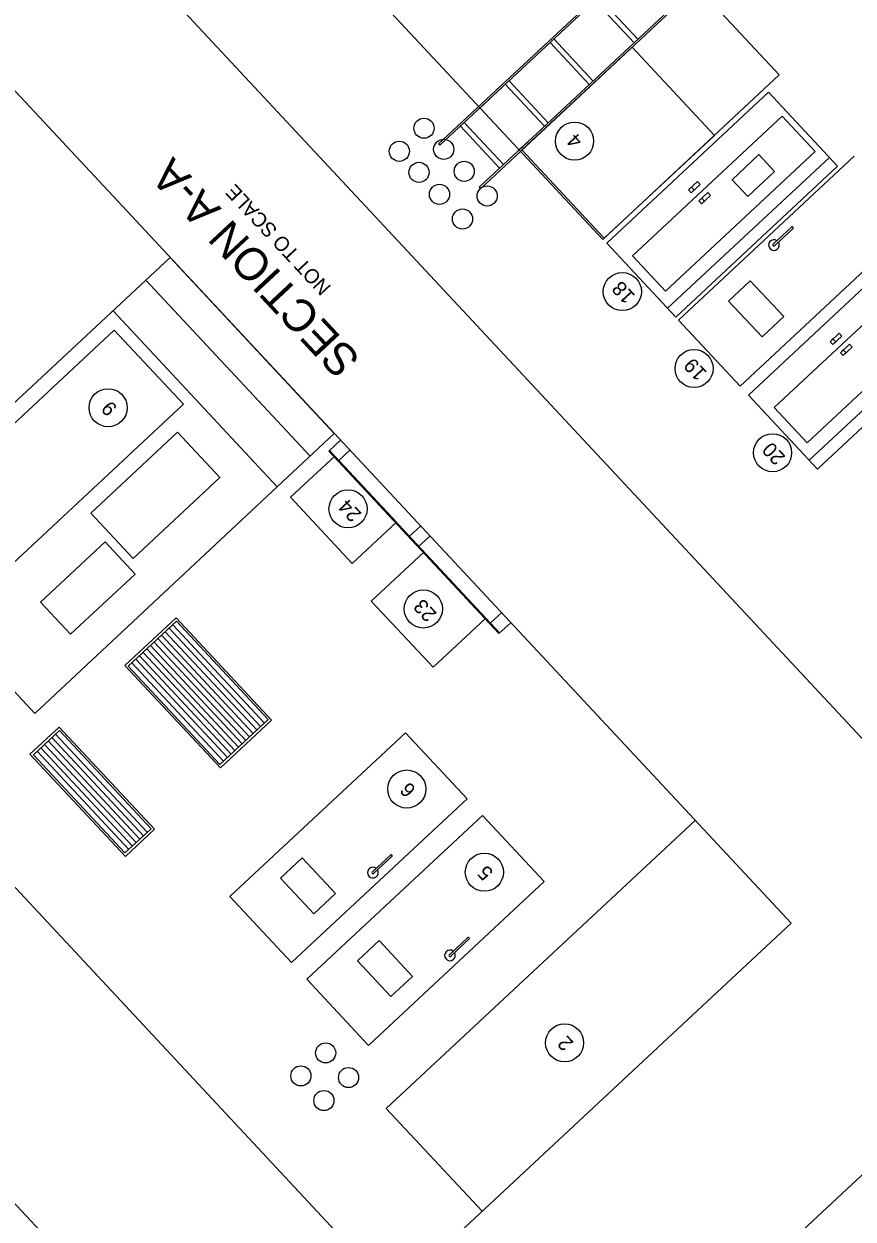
# Model space of a CAD drawing. Extents: x 1121979 to 1130574, y 1838676 to 1848573.
# Drawn here: x 1129646.59 to 1129660.33, y 1839345.74 to 1839365.55 of the extents above; entities that cross this region are included whole.
import ezdxf

# ---------------------------------------------------------------- set-up
doc = ezdxf.new("R2010")
doc.units = 0
for name, color, linetype in [('CLB-6', 7, 'Continuous'), ('GE-SHT-Clip Border', 7, 'Continuous'), ('GE-SHT-General', 7, 'Continuous'), ('HS_Dimensions and Text', 7, 'Continuous'), ('IPDC BUILDING RELATED', 7, 'Continuous'), ('IPDC-EXIST ELECT EQUIP', 7, 'Continuous'), ('IPDC-PROP ELECT CONDUIT', 7, 'Continuous'), ('IPDC-PROP ELECT EQUIP', 7, 'Continuous'), ('Level 4', 7, 'Continuous'), ('Sheets_General Details', 7, 'Continuous'), ('Sheets_Printer Plotting Border', 7, 'Continuous')]:
    doc.layers.add(name, color=color, linetype=linetype)

# ---------------------------------------------------------------- blocks, each defined once
blk = doc.blocks.new('CLB_61')
at = {"layer": 'CLB-6'}
for p, q in [((0.095, 18.288), (0, 18.288)), ((0, 18.288), (0, 0)), ((0.095, 18.288), (0.095, 0)), ((3.048, 18.288), (2.953, 18.288)), ((2.953, 18.288), (2.953, 0)), ((3.048, 18.288), (3.048, 0)), ((0.095, 16.891), (2.953, 16.891)), ((0.095, 16.637), (2.953, 16.637)), ((0.098, 15.621), (0.098, 14.859)), ((0.095, 13.843), (2.953, 13.843)), ((0.095, 13.589), (2.953, 13.589)), ((0.095, 10.795), (2.953, 10.795)), ((0.095, 10.541), (2.953, 10.541)), ((0.095, 7.747), (2.953, 7.747)), ((0.095, 7.493), (2.953, 7.493)), ((0.095, 4.699), (2.953, 4.699)), ((0.095, 4.445), (2.953, 4.445)), ((0.098, 3.429), (0.098, 2.667)), ((2.95, 2.667), (2.95, 3.429)), ((0.095, 1.651), (2.953, 1.651)), ((0.095, 1.397), (2.953, 1.397)), ((0.095, 0), (0, 0)), ((3.048, 0), (2.953, 0))]:
    blk.add_line(p, q, dxfattribs=at)

msp = doc.modelspace()

# ---------------------------------------------------------------- linework, layer by layer
at = {"layer": 'GE-SHT-Clip Border'}
msp.add_lwpolyline([(1129652.729, 1839339.252), (1129609.766, 1839385.33), (1129639.021, 1839412.608), (1129681.985, 1839366.531)], close=True, dxfattribs=at)
msp.add_lwpolyline([(1129652.729, 1839339.252), (1129609.766, 1839385.33), (1129639.021, 1839412.608), (1129681.985, 1839366.531)], close=True, dxfattribs=at)
msp.add_lwpolyline([(1129652.729, 1839339.252), (1129609.766, 1839385.33), (1129639.021, 1839412.608), (1129681.985, 1839366.531)], close=True, dxfattribs=at)
at = {"layer": 'GE-SHT-General'}
msp.add_lwpolyline([(1129652.729, 1839339.252), (1129609.766, 1839385.33), (1129640.484, 1839413.972), (1129683.448, 1839367.895)], close=True, dxfattribs=at)
at = {"layer": 'IPDC BUILDING RELATED'}
for p, q in [((1129642.1, 1839373.419), (1129661.457, 1839352.656)), ((1129639.942, 1839371.407), (1129659.302, 1839350.647)), ((1129652.719, 1839344.509), (1129633.359, 1839365.269)), ((1129659.302, 1839350.647), (1129652.719, 1839344.509))]:
    msp.add_line(p, q, dxfattribs=at)
at = {"layer": 'IPDC-EXIST ELECT EQUIP'}
for p, q in [((1129652.389, 1839371.914), (1129659.107, 1839364.708)), ((1129656.182, 1839361.98), (1129649.463, 1839369.186)), ((1129659.107, 1839364.708), (1129656.182, 1839361.98)), ((1129644.042, 1839357.05), (1129649.01, 1839361.682)), ((1129649.01, 1839361.682), (1129651.73, 1839358.766)), ((1129651.33, 1839358.391), (1129648.61, 1839361.309)), ((1129650.785, 1839357.882), (1129648.064, 1839360.8)), ((1129644.456, 1839357.097), (1129648.085, 1839360.48)), ((1129648.085, 1839360.48), (1129649.232, 1839359.249)), ((1129645.604, 1839355.866), (1129649.232, 1839359.249)), ((1129651.73, 1839358.766), (1129646.77, 1839354.124)), ((1129647.695, 1839357.446), (1129649.133, 1839358.787)), ((1129649.133, 1839358.787), (1129649.834, 1839358.035)), ((1129651.836, 1839358.653), (1129651.641, 1839358.472)), ((1129654.473, 1839355.458), (1129651.653, 1839358.482)), ((1129651.991, 1839358.487), (1129651.808, 1839358.317)), ((1129651.008, 1839357.708), (1129651.739, 1839358.39)), ((1129654.461, 1839355.448), (1129651.641, 1839358.472)), ((1129652.762, 1839357.293), (1129651.739, 1839358.39)), ((1129649.834, 1839358.035), (1129648.396, 1839356.694)), ((1129652.03, 1839356.611), (1129651.008, 1839357.708)), ((1129648.396, 1839356.694), (1129647.695, 1839357.446)), ((1129652.762, 1839357.293), (1129652.03, 1839356.611)), ((1129653.162, 1839357.231), (1129652.979, 1839357.061)), ((1129646.77, 1839354.124), (1129644.042, 1839357.05)), ((1129646.865, 1839355.97), (1129647.935, 1839356.967)), ((1129648.43, 1839356.436), (1129647.935, 1839356.967)), ((1129653.316, 1839357.065), (1129653.122, 1839356.884)), ((1129653.208, 1839356.792), (1129652.345, 1839355.987)), ((1129654.231, 1839355.695), (1129653.208, 1839356.792)), ((1129647.36, 1839355.439), (1129648.43, 1839356.436)), ((1129647.36, 1839355.439), (1129646.865, 1839355.97)), ((1129653.368, 1839354.89), (1129652.345, 1839355.987)), ((1129648.261, 1839354.919), (1129649.11, 1839355.71)), ((1129650.692, 1839354.013), (1129649.11, 1839355.71)), ((1129654.501, 1839355.795), (1129654.318, 1839355.624)), ((1129648.317, 1839354.907), (1129649.118, 1839355.654)), ((1129650.511, 1839353.909), (1129648.993, 1839355.538)), ((1129650.573, 1839353.966), (1129649.054, 1839355.595)), ((1129650.636, 1839354.025), (1129649.118, 1839355.654)), ((1129654.231, 1839355.695), (1129653.368, 1839354.89)), ((1129654.656, 1839355.629), (1129654.461, 1839355.448)), ((1129650.327, 1839353.737), (1129648.808, 1839355.366)), ((1129650.389, 1839353.794), (1129648.87, 1839355.423)), ((1129650.45, 1839353.851), (1129648.931, 1839355.48)), ((1129650.081, 1839353.508), (1129648.563, 1839355.137)), ((1129650.143, 1839353.565), (1129648.624, 1839355.194)), ((1129650.204, 1839353.622), (1129648.685, 1839355.251)), ((1129650.266, 1839353.679), (1129648.747, 1839355.308)), ((1129649.844, 1839353.222), (1129648.261, 1839354.919)), ((1129649.897, 1839353.336), (1129648.378, 1839354.965)), ((1129649.959, 1839353.393), (1129648.44, 1839355.022)), ((1129650.02, 1839353.45), (1129648.501, 1839355.079)), ((1129649.836, 1839353.278), (1129648.317, 1839354.907)), ((1129649.836, 1839353.278), (1129650.636, 1839354.025)), ((1129649.844, 1839353.222), (1129650.692, 1839354.013)), ((1129646.688, 1839353.452), (1129647.169, 1839353.9)), ((1129646.744, 1839353.441), (1129647.177, 1839353.844)), ((1129648.631, 1839352.155), (1129647.112, 1839353.784)), ((1129648.751, 1839352.204), (1129647.169, 1839353.9)), ((1129648.695, 1839352.215), (1129647.177, 1839353.844)), ((1129650, 1839351.089), (1129652.911, 1839353.803)), ((1129653.931, 1839352.708), (1129652.911, 1839353.803)), ((1129648.385, 1839351.926), (1129646.866, 1839353.555)), ((1129648.447, 1839351.983), (1129646.928, 1839353.612)), ((1129648.508, 1839352.041), (1129646.989, 1839353.67)), ((1129648.57, 1839352.098), (1129647.051, 1839353.727)), ((1129648.27, 1839351.755), (1129646.688, 1839353.452)), ((1129648.262, 1839351.812), (1129646.744, 1839353.441)), ((1129648.324, 1839351.869), (1129646.805, 1839353.498)), ((1129651.021, 1839349.995), (1129653.931, 1839352.708)), ((1129651.279, 1839349.718), (1129654.189, 1839352.432)), ((1129657.711, 1839352.353), (1129652.591, 1839347.579)), ((1129655.21, 1839351.337), (1129654.189, 1839352.432)), ((1129648.262, 1839351.812), (1129648.695, 1839352.215)), ((1129648.27, 1839351.755), (1129648.751, 1839352.204)), ((1129652.366, 1839351.502), (1129652.668, 1839351.784)), ((1129652.388, 1839351.478), (1129652.69, 1839351.76)), ((1129650.838, 1839351.395), (1129651.198, 1839351.731)), ((1129651.198, 1839351.731), (1129651.751, 1839351.138)), ((1129651.391, 1839350.802), (1129650.838, 1839351.395)), ((1129652.299, 1839348.623), (1129655.21, 1839351.337)), ((1129651.021, 1839349.995), (1129650, 1839351.089)), ((1129651.751, 1839351.138), (1129651.391, 1839350.802)), ((1129653.645, 1839350.131), (1129653.947, 1839350.412)), ((1129653.667, 1839350.107), (1129653.969, 1839350.389)), ((1129652.117, 1839350.024), (1129652.476, 1839350.359)), ((1129652.476, 1839350.359), (1129653.03, 1839349.766)), ((1129652.67, 1839349.431), (1129652.117, 1839350.024)), ((1129653.03, 1839349.766), (1129652.67, 1839349.431)), ((1129652.299, 1839348.623), (1129651.279, 1839349.718)), ((1129652.591, 1839347.579), (1129654.182, 1839345.873))]:
    msp.add_line(p, q, dxfattribs=at)
for centre in [(1129653.218, 1839363.825), (1129653.545, 1839363.475), (1129652.809, 1839363.443), (1129653.135, 1839363.093), (1129653.885, 1839363.11), (1129653.475, 1839362.729), (1129654.265, 1839362.702), (1129653.856, 1839362.32), (1129651.588, 1839348.498), (1129651.178, 1839348.117), (1129651.968, 1839348.09), (1129651.559, 1839347.708)]:
    msp.add_circle(centre, 0.167, dxfattribs=at)
for centre, radius, start, end in [((1129652.673, 1839351.766), 0.0183, 339.5896, 106.4047), ((1129652.371, 1839351.486), 0.0887, 52.4771, 31.2221), ((1129652.372, 1839351.485), 0.018, 108.471, 337.5232), ((1129653.952, 1839350.395), 0.0183, 339.5896, 106.4047), ((1129653.649, 1839350.115), 0.0887, 52.4771, 31.2221), ((1129653.65, 1839350.114), 0.018, 108.471, 337.5232)]:
    msp.add_arc(centre, radius, start, end, dxfattribs=at)
at = {"layer": 'IPDC-PROP ELECT CONDUIT'}
for p, q in [((1129657.254, 1839360.84), (1129659.936, 1839363.341)), ((1129659.601, 1839358.323), (1129662.283, 1839360.823))]:
    msp.add_line(p, q, dxfattribs=at)
for points in [[(1129660.073, 1839363.194), (1129658.93, 1839364.42), (1129656.248, 1839361.92), (1129657.391, 1839360.693)], [(1129659.7, 1839363.44), (1129659.155, 1839364.025), (1129656.673, 1839361.711), (1129657.219, 1839361.126)], [(1129659.029, 1839363.11), (1129658.77, 1839363.387), (1129658.325, 1839362.972), (1129658.583, 1839362.695)], [(1129657.796, 1839362.894), (1129657.75, 1839362.943), (1129657.601, 1839362.804), (1129657.646, 1839362.755)], [(1129657.601, 1839362.804), (1129657.646, 1839362.755), (1129657.695, 1839362.8), (1129657.649, 1839362.849)], [(1129657.966, 1839362.711), (1129657.92, 1839362.76), (1129657.771, 1839362.621), (1129657.817, 1839362.572)], [(1129657.771, 1839362.621), (1129657.817, 1839362.572), (1129657.865, 1839362.617), (1129657.82, 1839362.666)], [(1129662.42, 1839360.676), (1129661.277, 1839361.903), (1129658.595, 1839359.402), (1129659.738, 1839358.176)], [(1129662.047, 1839360.923), (1129661.502, 1839361.508), (1129659.02, 1839359.194), (1129659.566, 1839358.609)], [(1129660.143, 1839360.377), (1129660.097, 1839360.426), (1129659.948, 1839360.287), (1129659.994, 1839360.238)], [(1129659.948, 1839360.287), (1129659.994, 1839360.238), (1129660.042, 1839360.283), (1129659.996, 1839360.332)], [(1129660.313, 1839360.194), (1129660.268, 1839360.243), (1129660.118, 1839360.104), (1129660.164, 1839360.055)], [(1129660.118, 1839360.104), (1129660.164, 1839360.055), (1129660.212, 1839360.1), (1129660.167, 1839360.149)]]:
    msp.add_lwpolyline(points, close=True, dxfattribs=at)
at = {"layer": 'IPDC-PROP ELECT EQUIP'}
for p, q in [((1129654.84, 1839363.464), (1129656.669, 1839365.169)), ((1129656.669, 1839365.169), (1129658.032, 1839363.706)), ((1129656.204, 1839362.001), (1129658.032, 1839363.706)), ((1129654.84, 1839363.464), (1129656.204, 1839362.001)), ((1129657.435, 1839360.646), (1129660.346, 1839363.36)), ((1129658.456, 1839359.551), (1129661.366, 1839362.265)), ((1129659.011, 1839361.907), (1129659.313, 1839362.188)), ((1129659.033, 1839361.883), (1129659.335, 1839362.165)), ((1129658.626, 1839361.295), (1129658.267, 1839360.959)), ((1129659.179, 1839360.702), (1129658.626, 1839361.295)), ((1129658.267, 1839360.959), (1129658.82, 1839360.366)), ((1129658.82, 1839360.366), (1129659.179, 1839360.702)), ((1129657.435, 1839360.646), (1129658.456, 1839359.551))]:
    msp.add_line(p, q, dxfattribs=at)
for centre, radius, start, end in [((1129659.318, 1839362.171), 0.0183, 339.5896, 106.4046), ((1129659.018, 1839361.888), 0.0887, 54.7722, 33.5172), ((1129659.016, 1839361.89), 0.018, 108.471, 337.5232)]:
    msp.add_arc(centre, radius, start, end, dxfattribs=at)
at = {"layer": 'Level 4'}
for centre in [(1129655.713, 1839363.611), (1129656.505, 1839361.117), (1129657.694, 1839359.842), (1129647.983, 1839359.192), (1129658.995, 1839358.446), (1129651.959, 1839357.516), (1129653.207, 1839355.857), (1129652.933, 1839352.872), (1129654.219, 1839351.493), (1129655.548, 1839348.665)]:
    msp.add_circle(centre, 0.316, dxfattribs=at)
at = {"layer": 'Sheets_Printer Plotting Border'}
for centre in [(1129653.218, 1839363.825), (1129653.545, 1839363.475), (1129652.809, 1839363.443), (1129653.135, 1839363.093), (1129653.885, 1839363.11), (1129653.475, 1839362.729), (1129654.265, 1839362.702), (1129653.856, 1839362.32), (1129651.588, 1839348.498), (1129651.178, 1839348.117), (1129651.968, 1839348.09), (1129651.559, 1839347.708)]:
    msp.add_circle(centre, 0.167, dxfattribs=at)

# ---------------------------------------------------------------- block references
at = {"layer": 'IPDC-EXIST ELECT EQUIP', "xscale": 0.3332999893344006, "yscale": -0.3332999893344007, "rotation": 132.99714502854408}
msp.add_blockref('CLB_61', (1129654.153, 1839362.823), dxfattribs=at)

# ---------------------------------------------------------------- texts
at = {"layer": 'HS_Dimensions and Text'}
msp.add_text('NOT TO SCALE', height=0.24, rotation=132.9971, dxfattribs=at).set_placement((1129651.69, 1839361.195))
at = {"layer": 'Level 4'}
for s, p in [('4', (1129655.861, 1839363.628)), ('18', (1129656.73, 1839361.051)), ('19', (1129657.92, 1839359.776)), ('9', (1129648.147, 1839359.193)), ('20', (1129659.221, 1839358.38)), ('24', (1129652.196, 1839357.437)), ('23', (1129653.442, 1839355.781)), ('6', (1129653.097, 1839352.872)), ('5', (1129654.381, 1839351.496)), ('2', (1129655.708, 1839348.669))]:
    msp.add_text(s, height=0.24, rotation=132.9971, dxfattribs=at).set_placement(p)
at = {"layer": 'Sheets_General Details'}
msp.add_text('SECTION A-A', height=0.53756, rotation=132.9971, dxfattribs=at).set_placement((1129652.186, 1839360.006))

doc.saveas('drawing.dxf')
